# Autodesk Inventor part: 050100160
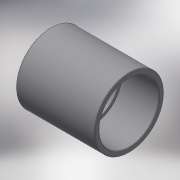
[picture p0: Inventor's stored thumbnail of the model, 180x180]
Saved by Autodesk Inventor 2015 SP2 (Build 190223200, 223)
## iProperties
Created: 2017-10
Part Number: 050100160
Material: Generic
Description: PLASSON SOCKET PVC 160 - CEMENT
Document SubType Name: Modeling
Designer: KIM
Density: 1 g/cm^3
Appearance: Default
Author: KIM
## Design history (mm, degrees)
derived "050100.ipt"
feature "Solid1::050100.ipt"
tag "TaggingFeature1"
body "Solid1"
other parameters: "d0" = 181, "d1" = 181, "d2" = 86, "d3" = 9, "d5" = 144, "d7" = 1.6, "E_" = 181, "H_" = 181, "l_" = 86, "Z_" = 9
